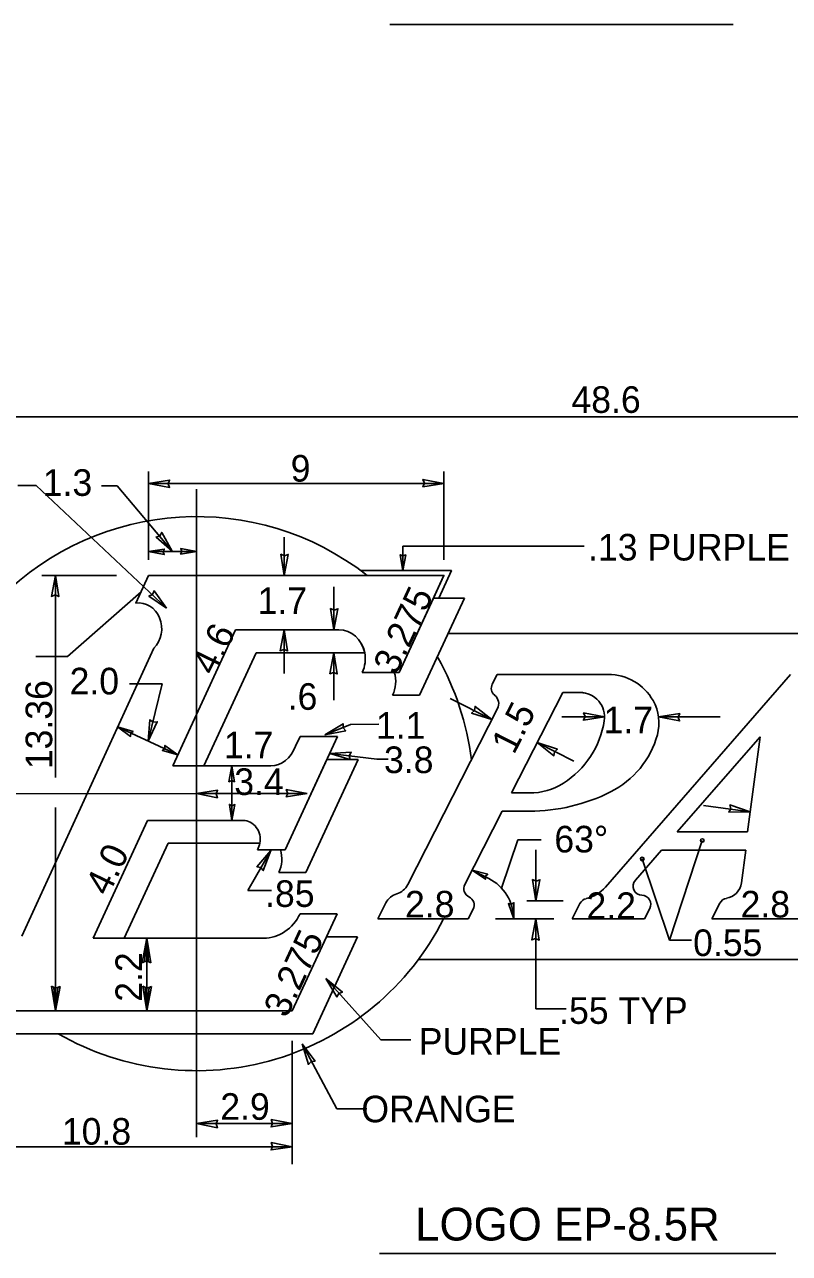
# Model space of a CAD drawing. Extents: x 10268197 to 10269179, y 2141503 to 2142677.
# Drawn here: x 10268600.98 to 10268621.1, y 2142084.85 to 2142117.18 of the extents above; entities that cross this region are included whole.
import ezdxf

# ---------------------------------------------------------------- set-up
doc = ezdxf.new("R2010")
doc.units = 0
for name, color, linetype in [('1', 7, 'Continuous'), ('2', 7, 'Continuous'), ('21', 7, 'Continuous'), ('3', 7, 'Continuous'), ('52', 7, 'Continuous'), ('TextDetails', 7, 'Continuous')]:
    doc.layers.add(name, color=color, linetype=linetype)

msp = doc.modelspace()

# ---------------------------------------------------------------- linework, layer by layer
at = {"layer": '1'}
for p, q in [((10268596.278, 2142106.859), (10268637.974, 2142106.859)), ((10268604.242, 2142103.1), (10268604.242, 2142105.423)), ((10268612.015, 2142103.1), (10268612.015, 2142105.423)), ((10268603.01, 2142105.049), (10268603.421, 2142105.049)), ((10268603.421, 2142105.049), (10268604.867, 2142103.33)), ((10268604.242, 2142105.11), (10268612.015, 2142105.11)), ((10268605.504, 2142096.949), (10268605.504, 2142104.956)), ((10268607.812, 2142102.689), (10268607.812, 2142103.695)), ((10268610.931, 2142102.816), (10268610.931, 2142103.463)), ((10268610.931, 2142103.463), (10268615.706, 2142103.463)), ((10268604.242, 2142103.316), (10268605.504, 2142103.316)), ((10268609.995, 2142102.689), (10268609.828, 2142102.816)), ((10268609.828, 2142102.816), (10268612.212, 2142102.816)), ((10268612.212, 2142102.816), (10268611.876, 2142102.087)), ((10268601.441, 2142102.689), (10268603.403, 2142102.689)), ((10268601.794, 2142097.372), (10268601.794, 2142102.689)), ((10268612.015, 2142102.689), (10268609.995, 2142102.689)), ((10268611.737, 2142102.087), (10268612.015, 2142102.689)), ((10268602.115, 2142100.561), (10268604.048, 2142102.262)), ((10268609.119, 2142101.258), (10268609.119, 2142102.39)), ((10268610.837, 2142100.139), (10268611.737, 2142102.087)), ((10268612.554, 2142102.087), (10268611.375, 2142099.536)), ((10268611.737, 2142102.087), (10268612.554, 2142102.087)), ((10268611.737, 2142102.087), (10268612.554, 2142102.087)), ((10268611.876, 2142102.087), (10268611.737, 2142102.087)), ((10268604.882, 2142097.677), (10268606.535, 2142101.258)), ((10268606.535, 2142101.258), (10268609.252, 2142101.258)), ((10268607.812, 2142100.112), (10268607.812, 2142101.258)), ((10268601.281, 2142100.561), (10268602.115, 2142100.561)), ((10268607.075, 2142100.655), (10268605.699, 2142097.677)), ((10268607.075, 2142100.655), (10268609.93, 2142100.655)), ((10268609.93, 2142100.655), (10268607.585, 2142100.655)), ((10268609.119, 2142099.412), (10268609.119, 2142100.655)), ((10268610.706, 2142100.139), (10268610.837, 2142100.139)), ((10268603.742, 2142099.841), (10268604.606, 2142099.841)), ((10268604.235, 2142098.331), (10268604.606, 2142099.841)), ((10268611.375, 2142099.536), (10268610.664, 2142099.536)), ((10268612.178, 2142099.456), (10268613.277, 2142098.896)), ((10268615.111, 2142098.967), (10268616.24, 2142098.967)), ((10268617.659, 2142098.967), (10268619.284, 2142098.967)), ((10268605.017, 2142097.97), (10268603.428, 2142098.703)), ((10268609.559, 2142098.77), (10268608.879, 2142098.5)), ((10268609.559, 2142098.77), (10268610.302, 2142098.774)), ((10268614.466, 2142098.291), (10268615.428, 2142097.801)), ((10268610.249, 2142097.857), (10268609.012, 2142098.009)), ((10268605.699, 2142097.677), (10268604.882, 2142097.677)), ((10268606.437, 2142096.246), (10268606.437, 2142097.677)), ((10268607.841, 2142095.473), (10268608.937, 2142097.848)), ((10268609.755, 2142097.848), (10268608.381, 2142094.872)), ((10268608.937, 2142097.848), (10268609.755, 2142097.848)), ((10268610.249, 2142097.857), (10268610.544, 2142097.858)), ((10268605.504, 2142096.949), (10268598.216, 2142096.938)), ((10268605.504, 2142087.909), (10268605.504, 2142096.949)), ((10268605.504, 2142096.949), (10268608.42, 2142096.949)), ((10268601.794, 2142091.236), (10268601.794, 2142096.588)), ((10268620.072, 2142096.474), (10268618.842, 2142096.634)), ((10268602.788, 2142093.144), (10268604.22, 2142096.246)), ((10268604.22, 2142096.246), (10268606.727, 2142096.246)), ((10268604.762, 2142095.643), (10268603.605, 2142093.144)), ((10268607.172, 2142095.643), (10268604.762, 2142095.643)), ((10268613.96, 2142095.737), (10268613.528, 2142094.464)), ((10268614.572, 2142095.737), (10268613.96, 2142095.737)), ((10268617.951, 2142093.092), (10268618.81, 2142095.718)), ((10268606.858, 2142094.401), (10268607.464, 2142095.449)), ((10268607.713, 2142095.473), (10268607.841, 2142095.473)), ((10268614.431, 2142094.131), (10268614.431, 2142095.473)), ((10268617.951, 2142093.092), (10268617.231, 2142095.23)), ((10268608.381, 2142094.872), (10268607.669, 2142094.872)), ((10268613.194, 2142094.716), (10268612.757, 2142094.94)), ((10268606.858, 2142094.401), (10268607.48, 2142094.401)), ((10268615.147, 2142094.131), (10268614.193, 2142094.131)), ((10268614.908, 2142093.655), (10268613.369, 2142093.655)), ((10268614.431, 2142093.655), (10268614.431, 2142091.286)), ((10268603.605, 2142093.144), (10268602.788, 2142093.144)), ((10268604.2, 2142091.236), (10268604.2, 2142093.144)), ((10268608.922, 2142093.184), (10268608.023, 2142091.236)), ((10268608.561, 2142090.632), (10268609.74, 2142093.184)), ((10268609.74, 2142093.184), (10268608.922, 2142093.184)), ((10268618.522, 2142093.092), (10268617.951, 2142093.092)), ((10268608.909, 2142092.085), (10268610.35, 2142090.469)), ((10268608.023, 2142091.236), (10268600.185, 2142091.236)), ((10268614.431, 2142091.286), (10268615.225, 2142091.286)), ((10268599.906, 2142090.632), (10268608.561, 2142090.632)), ((10268608.023, 2142087.201), (10268608.023, 2142090.443)), ((10268610.35, 2142090.469), (10268611.143, 2142090.469)), ((10268608.286, 2142090.365), (10268609.193, 2142088.659)), ((10268609.193, 2142088.659), (10268609.986, 2142088.659)), ((10268605.504, 2142088.268), (10268608.023, 2142088.268)), ((10268598.789, 2142087.662), (10268608.023, 2142087.662))]:
    msp.add_line(p, q, dxfattribs=at)
msp.add_lwpolyline([(10268600.808, 2142105.052), (10268601.286, 2142105.052), (10268604.718, 2142101.83)], dxfattribs=at)
msp.add_lwpolyline([(10268609.828, 2142102.816), (10268609.995, 2142102.689), (10268612.015, 2142102.689), (10268611.737, 2142102.087), (10268611.876, 2142102.087), (10268612.212, 2142102.816)], close=True, dxfattribs=at)
for centre in [(10268618.809, 2142095.717), (10268617.231, 2142095.23)]:
    msp.add_circle(centre, 0.0476, dxfattribs=at)
msp.add_arc((10268612.654, 2142093.655), 1.191, 0, 62.9941, dxfattribs=at)
for centre, major_axis, start_param, end_param in [((10268609.252, 2142100.494), (0, 0.764), 4.924772, 6.283185), ((10268610.052, 2142099.892), (0, 0.764), 4.227342, 5.041732), ((10268606.726, 2142095.744), (0, 0.502), 4.510784, 6.283185), ((10268607.057, 2142095.227), (0, 0.764), 4.227342, 5.041732)]:
    msp.add_ellipse(centre, major_axis=major_axis, ratio=0.906667, start_param=start_param, end_param=end_param, dxfattribs=at)
at = {"layer": '2'}
for p, q in [((10268609.828, 2142102.816), (10268612.212, 2142102.816)), ((10268612.212, 2142102.816), (10268611.876, 2142102.087)), ((10268604.242, 2142102.689), (10268603.906, 2142101.96)), ((10268604.242, 2142102.689), (10268612.015, 2142102.689)), ((10268612.015, 2142102.689), (10268610.837, 2142100.139)), ((10268612.554, 2142102.087), (10268611.375, 2142099.536)), ((10268611.737, 2142102.087), (10268612.554, 2142102.087)), ((10268604.882, 2142097.677), (10268606.535, 2142101.258)), ((10268606.535, 2142101.258), (10268609.252, 2142101.258)), ((10268637.974, 2142101.158), (10268612.125, 2142101.158)), ((10268600.913, 2142093.196), (10268604.387, 2142100.777)), ((10268607.075, 2142100.655), (10268605.699, 2142097.677)), ((10268609.93, 2142100.655), (10268607.075, 2142100.655)), ((10268610.837, 2142100.139), (10268609.865, 2142100.139)), ((10268613.416, 2142100.086), (10268613.286, 2142099.831)), ((10268616.334, 2142100.086), (10268613.416, 2142100.086)), ((10268616.262, 2142094.49), (10268621.126, 2142100.086)), ((10268610.664, 2142099.536), (10268611.375, 2142099.536)), ((10268613.79, 2142096.966), (10268615.138, 2142099.61)), ((10268613.79, 2142096.966), (10268615.138, 2142099.609)), ((10268615.138, 2142099.61), (10268615.597, 2142099.61)), ((10268615.138, 2142099.609), (10268615.597, 2142099.609)), ((10268613.424, 2142099.186), (10268611.066, 2142094.556)), ((10268609.216, 2142098.451), (10268607.841, 2142095.473)), ((10268608.23, 2142098.451), (10268608.113, 2142098.198)), ((10268608.23, 2142098.451), (10268609.216, 2142098.451)), ((10268620.329, 2142098.443), (10268618.153, 2142095.941)), ((10268620.329, 2142098.442), (10268618.153, 2142095.941)), ((10268620.002, 2142095.941), (10268620.329, 2142098.443)), ((10268620.002, 2142095.941), (10268620.329, 2142098.442)), ((10268604.882, 2142097.677), (10268607.462, 2142097.677)), ((10268607.462, 2142097.677), (10268604.882, 2142097.677)), ((10268609.755, 2142097.848), (10268608.381, 2142094.872)), ((10268608.937, 2142097.848), (10268609.755, 2142097.848)), ((10268614.262, 2142096.966), (10268613.79, 2142096.966)), ((10268614.262, 2142096.966), (10268613.79, 2142096.966)), ((10268612.562, 2142094.556), (10268613.547, 2142096.489)), ((10268613.547, 2142096.489), (10268614.262, 2142096.489)), ((10268602.788, 2142093.144), (10268604.22, 2142096.246)), ((10268604.22, 2142096.246), (10268606.727, 2142096.246)), ((10268618.153, 2142095.941), (10268620.002, 2142095.941)), ((10268618.153, 2142095.941), (10268620.002, 2142095.941)), ((10268604.762, 2142095.643), (10268603.605, 2142093.144)), ((10268607.172, 2142095.643), (10268604.762, 2142095.643)), ((10268607.109, 2142095.473), (10268607.841, 2142095.473)), ((10268617.741, 2142095.464), (10268617.05, 2142094.67)), ((10268619.953, 2142095.464), (10268617.741, 2142095.464)), ((10268619.84, 2142094.604), (10268619.953, 2142095.464)), ((10268608.381, 2142094.872), (10268607.669, 2142094.872)), ((10268610.486, 2142094.074), (10268610.273, 2142093.654)), ((10268615.384, 2142093.654), (10268615.591, 2142094.062)), ((10268619.06, 2142093.654), (10268619.271, 2142094.067)), ((10268609.202, 2142093.788), (10268608.023, 2142091.236)), ((10268608.23, 2142093.788), (10268609.202, 2142093.788)), ((10268612.654, 2142093.654), (10268612.783, 2142093.909)), ((10268617.431, 2142093.929), (10268617.291, 2142093.654)), ((10268610.273, 2142093.654), (10268612.654, 2142093.654)), ((10268617.291, 2142093.654), (10268615.384, 2142093.654)), ((10268621.442, 2142093.654), (10268619.06, 2142093.654)), ((10268603.605, 2142093.144), (10268602.788, 2142093.144)), ((10268603.605, 2142093.144), (10268607.269, 2142093.144)), ((10268609.74, 2142093.184), (10268608.561, 2142090.632)), ((10268608.922, 2142093.184), (10268609.74, 2142093.184)), ((10268611.339, 2142092.582), (10268633.605, 2142092.582)), ((10268598.763, 2142091.236), (10268608.023, 2142091.236)), ((10268599.906, 2142090.632), (10268608.561, 2142090.632))]:
    msp.add_line(p, q, dxfattribs=at)
for centre, radius, start, end in [((10268605.504, 2142096.949), 7.288, 51.9618, 218.2529), ((10268605.504, 2142096.949), 7.288, 7.0123, 29.4243), ((10268613.498, 2142099.723), 0.238, 152.9784, 231.1602), ((10268616.334, 2142098.728), 1.358, 29.4315, 90), ((10268613.169, 2142099.315), 0.286, 333.0027, 51.1602), ((10268615.596, 2142098.967), 0.643, 351.076, 90), ((10268615.596, 2142098.966), 0.643, 351.076, 90), ((10268616.479, 2142098.81), 1.191, 344.7074, 29.4315), ((10268613.879, 2142099.236), 2.382, 302.4206, 351.076), ((10268613.879, 2142099.236), 2.382, 302.4206, 351.076), ((10268615.33, 2142099.124), 2.382, 296.6431, 344.7074), ((10268614.262, 2142098.633), 1.667, 270, 302.4206), ((10268614.262, 2142098.633), 1.667, 270, 302.4206), ((10268614.262, 2142101.253), 4.764, 270, 296.6431), ((10268617.229, 2142094.514), 0.238, 138.9824, 268.6869), ((10268610.911, 2142093.858), 0.476, 106.4317, 152.9742), ((10268610.641, 2142094.772), 0.476, 286.4317, 332.9959), ((10268612.774, 2142094.448), 0.238, 152.9884, 244.7832), ((10268615.542, 2142095.116), 0.953, 282.7162, 318.9966), ((10268619.368, 2142094.665), 0.476, 279.2397, 352.5632), ((10268612.571, 2142094.017), 0.238, 333.0239, 64.7832), ((10268615.804, 2142093.954), 0.238, 102.7162, 153.0239), ((10268617.218, 2142094.038), 0.238, 332.9784, 88.6869), ((10268619.483, 2142093.96), 0.238, 99.2397, 153.0239), ((10268605.504, 2142096.949), 7.288, 240.0889, 333.1198)]:
    msp.add_arc(centre, radius, start, end, dxfattribs=at)
for centre, major_axis, ratio, start_param, end_param in [((10268603.986, 2142101.287), (0, 0.68), 0.889671, 3.865417, 6.41824), ((10268609.252, 2142100.494), (0, 0.764), 0.906667, 4.924065, 6.283185), ((10268609.252, 2142100.494), (0, 0.764), 0.906667, 4.924772, 6.283185), ((10268609.252, 2142100.494), (0, 0.764), 0.906667, 4.228038, 4.924065), ((10268610.052, 2142099.892), (0, 0.764), 0.906667, 4.227342, 5.041732), ((10268607.462, 2142098.633), (0, 0.955), 0.764971, 3.141593, 4.241405), ((10268606.726, 2142095.744), (0, 0.502), 0.906667, 4.510784, 6.283185), ((10268606.726, 2142095.744), (0, 0.502), 0.906667, 4.144801, 4.510784), ((10268607.057, 2142095.227), (0, 0.764), 0.906667, 4.227342, 5.041732), ((10268607.269, 2142094.338), (0, 1.193), 0.906667, 3.141593, 4.233038)]:
    msp.add_ellipse(centre, major_axis=major_axis, ratio=ratio, start_param=start_param, end_param=end_param, dxfattribs=at)
at = {"layer": '21'}
msp.add_line((10268610.316, 2142084.854), (10268620.747, 2142084.854), dxfattribs=at)
at = {"layer": '3'}
for p, q in [((10268604.882, 2142097.677), (10268606.535, 2142101.258)), ((10268606.535, 2142101.258), (10268609.252, 2142101.258)), ((10268606.535, 2142101.258), (10268609.252, 2142101.258)), ((10268607.045, 2142101.258), (10268606.535, 2142101.258)), ((10268609.252, 2142101.258), (10268607.045, 2142101.258)), ((10268607.075, 2142100.655), (10268605.699, 2142097.677)), ((10268609.93, 2142100.655), (10268607.075, 2142100.655)), ((10268604.882, 2142097.677), (10268607.462, 2142097.677)), ((10268607.462, 2142097.677), (10268604.882, 2142097.677)), ((10268605.393, 2142097.677), (10268606.211, 2142097.677))]:
    msp.add_line(p, q, dxfattribs=at)
msp.add_ellipse((10268609.252, 2142100.494), major_axis=(0, 0.764), ratio=0.906667, start_param=4.924772, end_param=6.283185, dxfattribs=at)
at = {"layer": '52'}
for p, q in [((10268604.2, 2142093.144), (10268604.074, 2142092.502)), ((10268604.2, 2142093.144), (10268604.135, 2142092.527)), ((10268604.2, 2142093.144), (10268604.302, 2142092.498)), ((10268604.2, 2142093.144), (10268604.243, 2142092.525)), ((10268604.074, 2142092.502), (10268604.189, 2142092.549)), ((10268604.189, 2142092.549), (10268604.302, 2142092.498)), ((10268601.794, 2142091.236), (10268601.691, 2142091.883)), ((10268601.803, 2142091.831), (10268601.691, 2142091.883)), ((10268601.794, 2142091.236), (10268601.75, 2142091.855)), ((10268601.794, 2142091.236), (10268601.918, 2142091.878)), ((10268601.794, 2142091.236), (10268601.858, 2142091.854)), ((10268601.918, 2142091.878), (10268601.803, 2142091.831)), ((10268604.2, 2142091.236), (10268604.097, 2142091.883)), ((10268604.21, 2142091.831), (10268604.097, 2142091.883)), ((10268604.2, 2142091.236), (10268604.156, 2142091.855)), ((10268604.2, 2142091.236), (10268604.324, 2142091.878)), ((10268604.2, 2142091.236), (10268604.264, 2142091.854)), ((10268604.324, 2142091.878), (10268604.21, 2142091.831))]:
    msp.add_line(p, q, dxfattribs=at)
for points in [[(10268604.242, 2142105.11), (10268604.798, 2142105.197), (10268604.757, 2142105.102), (10268604.795, 2142105.003)], [(10268612.015, 2142105.11), (10268611.459, 2142105.022), (10268611.501, 2142105.117), (10268611.463, 2142105.216)], [(10268604.867, 2142103.33), (10268604.442, 2142103.699), (10268604.542, 2142103.729), (10268604.593, 2142103.822)], [(10268604.242, 2142103.316), (10268604.659, 2142103.382), (10268604.628, 2142103.31), (10268604.656, 2142103.236)], [(10268605.504, 2142103.316), (10268605.086, 2142103.251), (10268605.118, 2142103.322), (10268605.09, 2142103.396)], [(10268607.812, 2142102.689), (10268607.725, 2142103.246), (10268607.82, 2142103.204), (10268607.919, 2142103.242)], [(10268610.931, 2142102.816), (10268610.865, 2142103.234), (10268610.937, 2142103.202), (10268611.011, 2142103.231)], [(10268601.794, 2142102.689), (10268601.881, 2142102.133), (10268601.786, 2142102.175), (10268601.687, 2142102.137)], [(10268604.718, 2142101.83), (10268604.252, 2142102.147), (10268604.348, 2142102.188), (10268604.388, 2142102.286)], [(10268609.119, 2142101.258), (10268609.032, 2142101.815), (10268609.127, 2142101.773), (10268609.226, 2142101.811)], [(10268607.812, 2142101.258), (10268607.9, 2142100.702), (10268607.805, 2142100.744), (10268607.705, 2142100.706)], [(10268609.119, 2142100.655), (10268609.207, 2142100.098), (10268609.112, 2142100.14), (10268609.013, 2142100.102)], [(10268613.277, 2142098.896), (10268612.741, 2142099.07), (10268612.821, 2142099.136), (10268612.833, 2142099.242)], [(10268604.235, 2142098.331), (10268604.282, 2142098.892), (10268604.365, 2142098.828), (10268604.471, 2142098.842)], [(10268616.24, 2142098.967), (10268615.684, 2142098.879), (10268615.726, 2142098.975), (10268615.687, 2142099.074)], [(10268617.659, 2142098.967), (10268618.215, 2142099.055), (10268618.174, 2142098.96), (10268618.211, 2142098.86)], [(10268603.428, 2142098.703), (10268603.835, 2142098.588), (10268603.776, 2142098.536), (10268603.771, 2142098.456)], [(10268608.879, 2142098.5), (10268609.363, 2142098.787), (10268609.36, 2142098.683), (10268609.432, 2142098.605)], [(10268605.017, 2142097.97), (10268604.61, 2142098.085), (10268604.669, 2142098.137), (10268604.674, 2142098.216)], [(10268614.466, 2142098.291), (10268615.001, 2142098.116), (10268614.921, 2142098.051), (10268614.909, 2142097.945)], [(10268609.012, 2142098.009), (10268609.574, 2142098.037), (10268609.523, 2142097.946), (10268609.55, 2142097.844)], [(10268606.437, 2142097.677), (10268606.503, 2142097.26), (10268606.431, 2142097.292), (10268606.357, 2142097.263)], [(10268605.504, 2142096.949), (10268606.061, 2142097.037), (10268606.019, 2142096.942), (10268606.057, 2142096.843)], [(10268608.42, 2142096.949), (10268607.864, 2142096.862), (10268607.906, 2142096.957), (10268607.868, 2142097.056)], [(10268606.437, 2142096.246), (10268606.371, 2142096.664), (10268606.443, 2142096.632), (10268606.517, 2142096.661)], [(10268620.072, 2142096.474), (10268619.509, 2142096.459), (10268619.563, 2142096.548), (10268619.538, 2142096.651)], [(10268607.464, 2142095.449), (10268607.261, 2142094.924), (10268607.199, 2142095.008), (10268607.095, 2142095.024)], [(10268612.759, 2142094.933), (10268613.168, 2142094.828), (10268613.11, 2142094.775), (10268613.107, 2142094.695)], [(10268614.431, 2142094.131), (10268614.344, 2142094.687), (10268614.439, 2142094.645), (10268614.538, 2142094.683)], [(10268613.85, 2142093.658), (10268613.71, 2142094.056), (10268613.785, 2142094.039), (10268613.854, 2142094.08)], [(10268614.431, 2142093.655), (10268614.519, 2142093.098), (10268614.424, 2142093.14), (10268614.325, 2142093.102)], [(10268608.909, 2142092.085), (10268609.345, 2142091.728), (10268609.246, 2142091.696), (10268609.197, 2142091.602)], [(10268608.286, 2142090.365), (10268608.625, 2142089.915), (10268608.521, 2142089.907), (10268608.451, 2142089.827)], [(10268605.504, 2142088.268), (10268606.061, 2142088.356), (10268606.019, 2142088.261), (10268606.057, 2142088.162)], [(10268608.023, 2142088.268), (10268607.466, 2142088.181), (10268607.508, 2142088.276), (10268607.47, 2142088.375)], [(10268608.023, 2142087.662), (10268607.466, 2142087.575), (10268607.508, 2142087.67), (10268607.47, 2142087.769)]]:
    msp.add_lwpolyline(points, close=True, dxfattribs=at)
at = {"layer": 'TextDetails'}
msp.add_line((10268610.594, 2142117.18), (10268619.619, 2142117.18), dxfattribs=at)

# ---------------------------------------------------------------- texts
at = {"layer": '1'}
for s, height, p in [('48.6', 0.7, (10268615.368, 2142106.965)), ('9', 0.7, (10268607.983, 2142105.157)), ('1.3', 0.7, (10268601.461, 2142104.782)), ('.13 PURPLE', 0.7, (10268615.805, 2142103.082)), ('1.7', 0.7, (10268607.114, 2142101.675)), ('2.0', 0.7, (10268602.167, 2142099.56)), ('.6', 0.7, (10268607.904, 2142099.154)), ('1.7', 0.7, (10268616.211, 2142098.538)), ('1.1', 0.7, (10268610.227, 2142098.393)), ('1.7', 0.7, (10268606.224, 2142097.878)), ('3.8', 0.7, (10268610.438, 2142097.49)), ('3.4', 0.7, (10268606.499, 2142096.914)), ('63°', 0.7, (10268614.918, 2142095.402)), ('.85', 0.7, (10268607.309, 2142093.969)), ('2.8', 0.7, (10268610.99, 2142093.691)), ('2.2', 0.7, (10268615.763, 2142093.651)), ('2.8', 0.7, (10268619.817, 2142093.691)), ('0.55', 0.7, (10268618.569, 2142092.677)), ('.55 TYP', 0.7, (10268615.044, 2142090.893)), ('PURPLE', 0.7, (10268611.351, 2142090.082)), ('2.9', 0.7, (10268606.131, 2142088.369)), ('ORANGE', 0.7, (10268609.842, 2142088.303)), ('10.8', 0.7, (10268601.964, 2142087.715)), ('LOGO EP-8.5R', 0.8624, (10268611.257, 2142085.194))]:
    msp.add_text(s, height=height, dxfattribs=at).set_placement(p)
for s, rotation, p in [('3.275', 65.0602, (10268610.762, 2142100.049)), ('4.6', 64.0244, (10268605.975, 2142100.028)), ('13.36', 90, (10268601.71, 2142097.592)), ('1.5', 62.9907, (10268613.856, 2142097.954)), ('4.0', 64.0244, (10268603.182, 2142094.228)), ('3.275', 65.0602, (10268607.879, 2142091.022)), ('2.2', 90, (10268604.073, 2142091.474))]:
    msp.add_text(s, height=0.7, rotation=rotation, dxfattribs=at).set_placement(p)

doc.saveas('drawing.dxf')
